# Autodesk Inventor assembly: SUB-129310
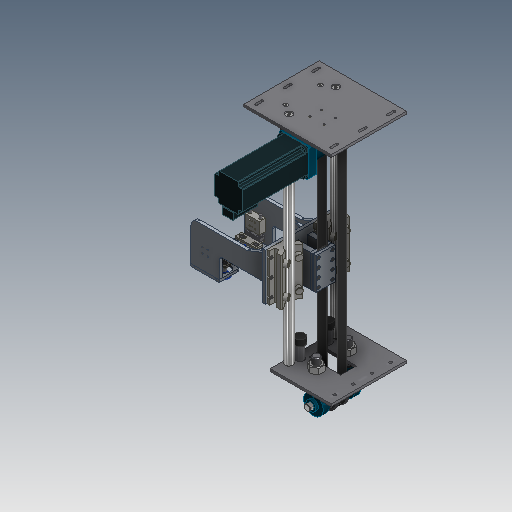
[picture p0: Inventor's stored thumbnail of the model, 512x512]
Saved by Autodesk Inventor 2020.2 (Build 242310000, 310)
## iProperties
Created: 1999-11
Part Number: SUB-129310
Document SubType Name: Assembly
Designer: sspink
Mass: 67369.6 g
Surface Area: 21706.2 cm^2
Volume: 12786.5 cm^3
Density: 5.26881 g/cm^3
Control State: 0
Master: False
Checked Out: False
Shininess: 0.0
Length Units: 11269
Angle Units: 11279
Time Units: 11290
Mass Units: 11283
Length Display Precision: 3
Angle Display Precision: 2
Compacted: True
Dimensions: 1051,2x644,7x575,4 mm
Mass: 67,37 kg
DocNumber: SUB-179310.iam
Folder: 01 - Themengebiete\Simplification\01 - Packaging machine\
VDS_Category: 3D Komponenten
VDS_NumSchm: Kein
Density: 0.0
Volumn: 0.0
Area: 0.0
PropertySet Name: Model Information
Author: sspink
Revision Number: -
Title: SUB-179310
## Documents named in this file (22)
- D:\07 - DEMODATEN\OTX 2019 - Dataset - UPDATE - Dez2019\Designs\07-Packing machine\SUB-129310.iam
- D:\07 - DEMODATEN\OTX 2019 - Dataset - UPDATE - Dez2019\Designs\07-Packing machine\Parts\ADSK-011674.ipt
- D:\07 - DEMODATEN\OTX 2019 - Dataset - UPDATE - Dez2019\Designs\07-Packing machine\Parts\ADSK-011397.ipt
- D:\07 - DEMODATEN\OTX 2019 - Dataset - UPDATE - Dez2019\Designs\07-Packing machine\Parts\ADSK-011751.ipt
- D:\07 - DEMODATEN\OTX 2019 - Dataset - UPDATE - Dez2019\Designs\07-Packing machine\Parts\ADSK-011675.ipt
- D:\07 - DEMODATEN\OTX 2019 - Dataset - UPDATE - Dez2019\Designs\07-Packing machine\Parts\ADSK-011300.ipt
- D:\07 - DEMODATEN\OTX 2019 - Dataset - UPDATE - Dez2019\Designs\07-Packing machine\Parts\ADSK-011305.ipt
- D:\07 - DEMODATEN\OTX 2019 - Dataset - UPDATE - Dez2019\Designs\07-Packing machine\500381.iam
- D:\07 - DEMODATEN\OTX 2019 - Dataset - UPDATE - Dez2019\Designs\07-Packing machine\Parts\ADSK-011314.ipt
- D:\07 - DEMODATEN\OTX 2019 - Dataset - UPDATE - Dez2019\Designs\07-Packing machine\Parts\ADSK-011773.ipt
- D:\07 - DEMODATEN\OTX 2019 - Dataset - UPDATE - Dez2019\Designs\07-Packing machine\Parts\ADSK-011343.ipt
- D:\07 - DEMODATEN\OTX 2019 - Dataset - UPDATE - Dez2019\Designs\07-Packing machine\Parts\ADSK-011811.ipt
- D:\07 - DEMODATEN\OTX 2019 - Dataset - UPDATE - Dez2019\Designs\07-Packing machine\Parts\ADSK-011235.ipt
- D:\07 - DEMODATEN\OTX 2019 - Dataset - UPDATE - Dez2019\Designs\07-Packing machine\A103445.iam
- D:\07 - DEMODATEN\OTX 2019 - Dataset - UPDATE - Dez2019\Content Center Files\de-DE\ISO 10642(1)\ISO 10642 - M8x25.ipt
- D:\07 - DEMODATEN\OTX 2019 - Dataset - UPDATE - Dez2019\Content Center Files\de-DE\ISO 10642(1)\ISO 10642 - M12x35.ipt
- D:\07 - DEMODATEN\OTX 2019 - Dataset - UPDATE - Dez2019\Content Center Files\de-DE\DIN 125-1  B\DIN 125-1 - B 8,4.ipt
- D:\07 - DEMODATEN\OTX 2019 - Dataset - UPDATE - Dez2019\Content Center Files\de-DE\DIN EN 24 017\ISO 4017 - M8 x 16DIN EN.ipt
- D:\07 - DEMODATEN\OTX 2019 - Dataset - UPDATE - Dez2019\Designs\07-Packing machine\ADSK-014167.iam
- D:\07 - DEMODATEN\OTX 2019 - Dataset - UPDATE - Dez2019\Content Center Files\de-DE\ISO 4032(2)\ISO 4032 - M30 - ISO.ipt
- D:\07 - DEMODATEN\OTX 2019 - Dataset - UPDATE - Dez2019\Content Center Files\de-DE\ISO 2491 - A\ISO 2491 - A  6 x 4 x 32.ipt
- D:\07 - DEMODATEN\OTX 2019 - Dataset - UPDATE - Dez2019\Designs\07-Packing machine\ADSK-014170.iam
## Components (45 placed, 21 different names)
1. ADSK-011300:1 — Insert:19, Passend:59, Passend:90
2. ADSK-011300:2 — Mate:31, Insert:20, Passend:60, Passend:91
3. ADSK-011343:1 — Mate:15, Mate:26, Mate:27, Mate:28, Insert:19, Insert:20, Mate:47, Mate:48, Passend:67, Passend:68, Passend:85, Passend:86
4. ADSK-011314:3 — Insert:11, Flush:8, Mate:35, Passend:92
5. ADSK-011314:4 — Insert:10, Mate:34, Flush:8, Passend:93
6. ADSK-011773:3 — Insert:10, Mate:13
7. ADSK-011773:4 — Insert:11, Mate:13, Passend:104
8. ADSK-011305:2 — Passend:103, Passend:104, Passend:105, Passend:106, Passend:107, Passend:111, Passend:114
9. ADSK-011811:1 — Insert:13, Insert:14, Mate:16, Mate:17, Angular, Mate:24, Passend:87, Passend:88, Passend:89, Passend:108
10. 1.5 inch timing belt.ipt:1 — Mate:24, Fluchtend:9, Passend:103, Passend:109, Passend:110, Passend:112, Passend:113
11. 500381:1 [sub-assembly] — Mate:15, Insert:13, Insert:14, Passend:67, Passend:68, Passend:70, Passend:72, Passend:74, Passend:76, Passend:87, Passend:88, Passend:89
12. A103445:1 [sub-assembly] — Mate:16, Mate:17, Angular
13. ADSK-011397:1 — Mate:31, Mate:34, Mate:35, Insert:29, Insert:30, Passend:59, Passend:60, Passend:92, Passend:93, Passend:95, Passend:97, Fluchtend:9
14. ADSK-011674:1 — Mate:47, Insert:26, Passend:86
15. ADSK-011674:2 — Mate:48, Insert:25, Passend:85
16. ADSK-011751:1 — Insert:26
17. ADSK-011751:2 — Insert:25
18. ADSK-011675:1 — Insert:27, Insert:29
19. ADSK-011675:2 — Insert:28, Insert:30
20. ADSK-011751:3 — Insert:28, STROKE
21. ADSK-011751:4 — Insert:27
22. ADSK-014170:1 [sub-assembly] — Passend:108, Passend:109, Passend:110
23. ADSK-014170:2 [sub-assembly] — Passend:111, Passend:112, Passend:113, Passend:114
24. ISO 2491 A A  6 x 4 x 32:1 — Passend:105, Passend:106, Passend:107
25. ISO 10642 M8x25:1
26. ISO 10642 M8x25:2
27. ISO 10642 M12x35:1
28. ISO 10642 M12x35:2
29. ISO 10642 M12x35:3
30. ISO 10642 M12x35:4
31. ISO 10642 M8x25:3
32. ISO 10642 M8x25:4
33. DIN 125-1 B B 8,4:1 — Passend:70, Passend:78, Passend:80, Passend:82, Passend:84
34. DIN 125-1 B B 8,4:2 — Passend:72
35. DIN 125-1 B B 8,4:3 — Passend:74
36. DIN 125-1 B B 8,4:4 — Passend:76
37. DIN EN 24017 M8 x 16:1 — Passend:78
38. DIN EN 24017 M8 x 16:2 — Passend:80
39. DIN EN 24017 M8 x 16:3 — Passend:82
40. DIN EN 24017 M8 x 16:4 — Passend:84
41. ADSK-014167:1 [sub-assembly] — Passend:90, Passend:91, STROKE
42. ISO 4032 M30:1 — Passend:95
43. ISO 4032 M30:2 — Passend:97
44. ISO 4032 M30:3
45. ISO 4032 M30:4
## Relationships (64: Mate 49, Insert 12, Flush 2, Angle 1)
- STROKE [Mate]: ADSK-011751:3 ↔ ADSK-014167:1
- Insert:10: ADSK-011314:4 ↔ ADSK-011773:3
- Insert:11: ADSK-011314:3 ↔ ADSK-011773:4
- Mate:13: ADSK-011773:3 ↔ ADSK-011773:4
- Mate:15: ADSK-011343:1 ↔ 500381:1
- Insert:13: ADSK-011811:1 ↔ 500381:1
- Insert:14: ADSK-011811:1 ↔ 500381:1
- Mate:16: ADSK-011811:1 ↔ A103445:1
- Mate:17: ADSK-011811:1 ↔ A103445:1
- Angular [Angle]: ADSK-011811:1 ↔ A103445:1
- Mate:24: ADSK-011811:1 ↔ 1.5 inch timing belt.ipt:1
- Mate:26: ADSK-011343:1
- Mate:27: ADSK-011343:1
- Mate:28: ADSK-011343:1
- Mate:31: ADSK-011300:2 ↔ ADSK-011397:1
- Mate:34: ADSK-011314:4 ↔ ADSK-011397:1
- Flush:8: ADSK-011314:3 ↔ ADSK-011314:4
- Mate:35: ADSK-011314:3 ↔ ADSK-011397:1
- Insert:19: ADSK-011300:1 ↔ ADSK-011343:1
- Insert:20: ADSK-011300:2 ↔ ADSK-011343:1
- Mate:47: ADSK-011343:1 ↔ ADSK-011674:1
- Mate:48: ADSK-011343:1 ↔ ADSK-011674:2
- Insert:25: ADSK-011674:2 ↔ ADSK-011751:2
- Insert:26: ADSK-011674:1 ↔ ADSK-011751:1
- Insert:27: ADSK-011675:1 ↔ ADSK-011751:4
- Insert:28: ADSK-011675:2 ↔ ADSK-011751:3
- Insert:29: ADSK-011397:1 ↔ ADSK-011675:1
- Insert:30: ADSK-011397:1 ↔ ADSK-011675:2
- Passend:59 [Mate]: ADSK-011300:1 ↔ ADSK-011397:1
- Passend:60 [Mate]: ADSK-011300:2 ↔ ADSK-011397:1
- Passend:67 [Mate]: ADSK-011343:1 ↔ 500381:1
- Passend:68 [Mate]: ADSK-011343:1 ↔ 500381:1
- Passend:70 [Mate]: 500381:1 ↔ DIN 125-1 B B 8,4:1
- Passend:72 [Mate]: 500381:1 ↔ DIN 125-1 B B 8,4:2
- Passend:74 [Mate]: 500381:1 ↔ DIN 125-1 B B 8,4:3
- Passend:76 [Mate]: 500381:1 ↔ DIN 125-1 B B 8,4:4
- Passend:78 [Mate]: DIN 125-1 B B 8,4:1 ↔ DIN EN 24017 M8 x 16:1
- Passend:80 [Mate]: DIN 125-1 B B 8,4:1 ↔ DIN EN 24017 M8 x 16:2
- Passend:82 [Mate]: DIN 125-1 B B 8,4:1 ↔ DIN EN 24017 M8 x 16:3
- Passend:84 [Mate]: DIN 125-1 B B 8,4:1 ↔ DIN EN 24017 M8 x 16:4
- Passend:85 [Mate]: ADSK-011343:1 ↔ ADSK-011674:2
- Passend:86 [Mate]: ADSK-011343:1 ↔ ADSK-011674:1
- Passend:87 [Mate]: ADSK-011811:1 ↔ 500381:1
- Passend:88 [Mate]: ADSK-011811:1 ↔ 500381:1
- Passend:89 [Mate]: ADSK-011811:1 ↔ 500381:1
- Passend:90 [Mate]: ADSK-011300:1 ↔ ADSK-014167:1
- Passend:91 [Mate]: ADSK-011300:2 ↔ ADSK-014167:1
- Passend:92 [Mate]: ADSK-011314:3 ↔ ADSK-011397:1
- Passend:93 [Mate]: ADSK-011314:4 ↔ ADSK-011397:1
- Passend:95 [Mate]: ADSK-011397:1 ↔ ISO 4032 M30:1
- Passend:97 [Mate]: ADSK-011397:1 ↔ ISO 4032 M30:2
- Fluchtend:9 [Flush]: 1.5 inch timing belt.ipt:1 ↔ ADSK-011397:1
- Passend:103 [Mate]: ADSK-011305:2 ↔ 1.5 inch timing belt.ipt:1
- Passend:104 [Mate]: ADSK-011773:4 ↔ ADSK-011305:2
- Passend:105 [Mate]: ADSK-011305:2 ↔ ISO 2491 A A  6 x 4 x 32:1
- Passend:106 [Mate]: ADSK-011305:2 ↔ ISO 2491 A A  6 x 4 x 32:1
- Passend:107 [Mate]: ADSK-011305:2 ↔ ISO 2491 A A  6 x 4 x 32:1
- Passend:108 [Mate]: ADSK-011811:1 ↔ ADSK-014170:1
- Passend:109 [Mate]: 1.5 inch timing belt.ipt:1 ↔ ADSK-014170:1
- Passend:110 [Mate]: 1.5 inch timing belt.ipt:1 ↔ ADSK-014170:1
- Passend:111 [Mate]: ADSK-011305:2 ↔ ADSK-014170:2
- Passend:112 [Mate]: 1.5 inch timing belt.ipt:1 ↔ ADSK-014170:2
- Passend:113 [Mate]: 1.5 inch timing belt.ipt:1 ↔ ADSK-014170:2
- Passend:114 [Mate]: ADSK-011305:2 ↔ ADSK-014170:2
